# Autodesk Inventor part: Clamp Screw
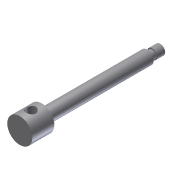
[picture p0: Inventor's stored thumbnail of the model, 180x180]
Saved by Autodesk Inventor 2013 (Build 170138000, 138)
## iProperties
Shininess: 77.0
Length Units: 11269
Angle Units: 11279
Time Units: 11290
Mass Units: 11283
Length Display Precision: 3
Angle Display Precision: 2
Created: 2002-02
Part Number: Clamp Screw
Document SubType Name: Modeling
Designer: ***
Density: 1 g/cm^3
Material: Generic
Density: 0.0
Volumn: 0.0
Area: 0.0
PropertySet Name: Model Information
Control State: 0
Master: False
Checked Out: False
Author: ***
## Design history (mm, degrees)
sketch "Sketch1"
  geometry: L1 (0, 140)-(5, 140); L2 (5, 140)-(5, 132); L3 (5, 132)-(4, 132); L4 (4, 132)-(4, 127); L5 (4, 127)-(6.5, 127); L6 (6.5, 127)-(6.5, 25); L7 (6.5, 25)-(4, 25); L8 (4, 25)-(4, 22); L9 (4, 22)-(12.5, 22); L10 (12.5, 22)-(12.5, 0); L11 (12.5, 0)-(0, 0); L12 (0, 0)-(0, 140)
  constraints: 24 end point, 10 parallel, 1 horizontal, 1 perpendicular
  dimensions: "d0" = 10 diameter of L2 L12; "d1" = 8 diameter of L4 L12; "d2" = 13 diameter of L6 L12; "d3" = 8 diameter of L7.end L12; "d4" = 25 diameter of L10 L12; "d5" = 3 distance from line of L7.end L9; "d6" = 8 distance of L1.end L2.end; "d7" = 13 vertical distance of L1.end L5.end; "d8" = 22 distance of L9.end L10.end; "d10" = 102 distance of L5.end L6.end
revolve "Revolution1" sketch "Sketch1" stored, may be unused: angle "d11" = 90 deg
sketch "Sketch3"
  geometry: L1 (-12.5, 0)-(12.5, 0) reference; C1 r 5 at (-0.113, 11)
  constraints: 1 centre point
  dimensions: "d13" = 10 diameter of C1; "d14" = 11 distance from line of L1 C1.centre
extrude "Extrusion1" cut sketch "Sketch3" stored distance "d15" = 10; taper "d16" = 0 deg
body "Solid1"
